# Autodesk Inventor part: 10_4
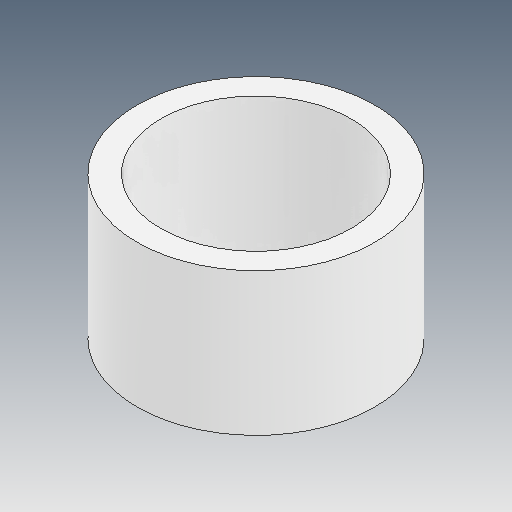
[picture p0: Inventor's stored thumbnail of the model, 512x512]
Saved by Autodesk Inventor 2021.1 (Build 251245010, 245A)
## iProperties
Created: 2021-06
Part Number: 10_4
Material: Ogólny
Document SubType Name: Modeling
Designer: user
Density: 1 g/cm^3
Appearance: Domyślna
Author: user
Revision Number: ÈÎºÎ
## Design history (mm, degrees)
feature "ÊäÈë1"
node "Bryła1"
